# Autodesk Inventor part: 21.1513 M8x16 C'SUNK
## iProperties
Created: 2006-12
Part Number: 21.1513 M8x16 C'SUNK
Material: Steel, Mild
Description: Hexagon socket countersunk head cap screws
Document SubType Name: Modeling
Standard: DIN 7991
Designer: Andy Moles
Standards Organization: DIN
Language: en-US
Size Designation: M8x16
Categories: <MemberInstance Version="R10.0.0"><Categories><Category DisplayName="Fasteners" InternalName="e4da775c-781d-43d5-af7c-5136215cf5a6" Mnemonic="FSTN"><Category Di
Mass: 8.27151 g
Surface Area: 8.26631 cm^2
Volume: 1.05235 cm^3
Density: 7.86 g/cm^3
Author: Andy Moles
Revision Number: 1
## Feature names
1. Revolution1
2. Extrusion1
3. Fillet1
4. Chamfer1
